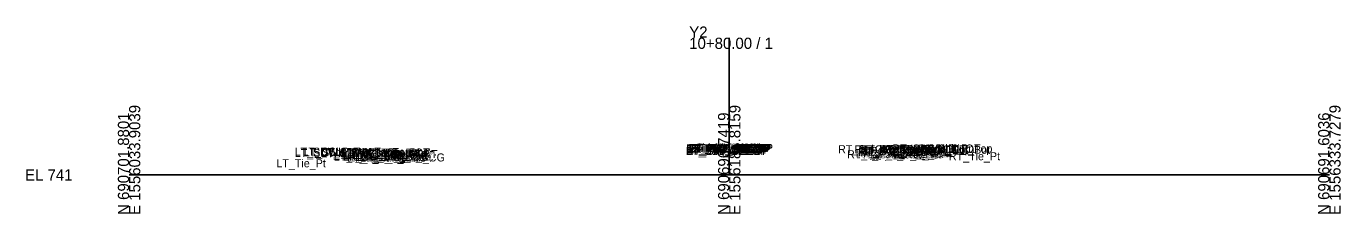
# Model space of a CAD drawing. Extents: x -26 to 4229, y -10 to 9523.
# Drawn here: x -25.7 to 302.8, y -9.7 to 37.1 of the extents above; entities that cross this region are included whole.
import ezdxf

# ---------------------------------------------------------------- set-up
doc = ezdxf.new("R2010")
doc.units = 0
doc.layers.add('Default', color=7, linetype='Continuous')
doc.layers.add('Exist Cross Section Cell', color=7, linetype='Continuous')

msp = doc.modelspace()

# ---------------------------------------------------------------- linework, layer by layer
at = {"layer": 'Exist Cross Section Cell'}
for p, q in [((150, 0), (150, 34.29)), ((0, 0), (150, 0)), ((150, 0), (300, 0))]:
    msp.add_line(p, q, dxfattribs=at)

# ---------------------------------------------------------------- texts
at = {"layer": 'Default'}
for s, height, p in [('LT_SDWK_Out_Top', 2, (41.38, 4.8)), ('LT_CSLP_Pnt', 2, (43.32, 4.83)), ('LT_Sub_Trench_Out_DLT', 2, (43.64, 4.63)), ('LT_SDWK_In_Top', 2, (48, 4.7)), ('LT_CG_Top_Face', 2, (52.9, 4.59)), ('LT_CG_Top_BOC', 2, (53.43, 4.59)), ('RT_Sub_OEEOP', 2, (139.17, 4.98)), ('LT_Sub_OEEOP', 2, (139.21, 4.98)), ('RT_PV2_OEEOP', 2, (139.26, 5.6)), ('RT_PV3_OEEOP', 2, (139.26, 5.35)), ('LT_PV2_OEEOP', 2, (139.31, 5.6)), ('LT_PV3_OEEOP', 2, (139.31, 5.35)), ('RT_PV1_OEEOP', 2, (139.83, 5.73)), ('LT_PV1_OEEOP', 2, (139.87, 5.73)), ('RT_PV2_IEEOP', 2, (139.91, 5.6)), ('LT_PV2_IEEOP', 2, (139.95, 5.6)), ('RT_PV1_IEEOP', 2, (140.47, 5.73)), ('LT_PV1_IEEOP', 2, (140.52, 5.73)), ('RT_PV2_PGL', 2, (141.17, 5.6)), ('LT_PV2_PGL', 2, (141.21, 5.6)), ('RT_PV1_PGL', 2, (141.73, 5.85)), ('LT_PV1_PGL', 2, (141.78, 5.85)), ('RT_Sub_Trench_Out_DLT', 2, (177.22, 5.43)), ('RT_CG_Top_Face', 2, (181.34, 5.39)), ('RT_PV2_OEOT', 2, (182.25, 4.76)), ('RT_CG_Top_Gut', 2, (182.31, 4.89)), ('RT_PV1_OEOT', 2, (182.81, 5.01)), ('RT_CG_Top_BOC', 2, (182.86, 5.39)), ('RT_SDWK_In_Top', 2, (187.43, 5.51)), ('RT_SDWK_In_Bot', 2, (187.47, 5.17)), ('RT_SDWK_Out_Top', 2, (190.81, 5.6)), ('RT_SDWK_Out_Bot', 2, (190.84, 5.27)), ('RT_Shld_O', 2, (197.16, 5.59)), ('CSLP_Pnt', 2, (199.49, 5.63)), ('LT_Tie_Pt', 2, (36.83, 1.91)), ('LT_SDWK_Out_Bot', 2, (41.41, 4.47)), ('LT_SDWK_In_Bot', 2, (48.03, 4.37)), ('LT_CG1_Shelf_Out', 2, (51.19, 3.56)), ('LT_CG_Bot_BOC', 2, (53.46, 3.57)), ('LT_CG_Top_Gut', 2, (53.88, 4.09)), ('LT_Sub_OEOP', 2, (54.5, 3.31)), ('LT_Sub_OEOT_CG', 2, (55.01, 3.37)), ('LT_CG_Bot_IE', 2, (57.56, 3.62)), ('LT_Sub_OEOT', 2, (57.72, 3.33)), ('LT_PV2_OEOT', 2, (57.82, 3.96)), ('LT_PV3_OEOT', 2, (57.82, 3.71)), ('LT_PV1_OEOT', 2, (58.38, 4.21)), ('RT_Sub_OEOT_CG', 2, (179.44, 4.18)), ('RT_CG1_Shelf_Out', 2, (181.63, 4.37)), ('RT_CG_Bot_IE', 2, (181.99, 4.43)), ('RT_Sub_OEOT', 2, (182.15, 4.14)), ('RT_PV3_OEOT', 2, (182.25, 4.51)), ('RT_CG_Bot_BOC', 2, (182.89, 4.38)), ('RT_Sub_OEOP', 2, (185.44, 4.11)), ('RT_Tie_Pt', 2, (204.9, 3.67)), ('-', 0.0001, (0, 0)), ('-', 0.0001, (0, 0)), ('-', 0.0001, (0, 0)), ('-', 0.0001, (0, 0)), ('-', 0.0001, (0, 0)), ('-', 0.0001, (0, 0)), ('-', 0.0001, (0, 0)), ('-', 0.0001, (0, 0)), ('-', 0.0001, (0, 0)), ('-', 0.0001, (0, 0))]:
    msp.add_text(s, height=height, dxfattribs=at).set_placement(p)
at = {"layer": 'Exist Cross Section Cell'}
for s, p in [('Y2', (140, 34.29)), ('10+80.00 / 1', (140, 31.49)), ('EL 741', (-26, -1.4))]:
    msp.add_text(s, height=2.8, dxfattribs=at).set_placement(p)
for s, p in [('E 1556033.9039', (2.8, -10)), ('E 1556183.8159', (152.8, -10)), ('E 1556333.7279', (302.8, -10)), ('N 690701.8801', (0, -10)), ('N 690696.7419', (150, -10)), ('N 690691.6036', (300, -10))]:
    msp.add_text(s, height=2.8, rotation=90, dxfattribs=at).set_placement(p)

doc.saveas('drawing.dxf')
